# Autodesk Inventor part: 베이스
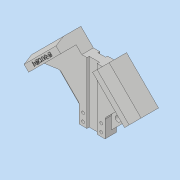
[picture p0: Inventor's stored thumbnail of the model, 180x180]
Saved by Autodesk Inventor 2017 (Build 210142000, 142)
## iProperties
Part Number: 베이스
Material: 일반
Document SubType Name: Modeling
Designer: 222
Density: 1 g/cm^3
Appearance: 기본값
Author: 222
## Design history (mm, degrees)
sketch "스케치1"
  geometry: L1 (-84.853, 0)-(0, 84.853); L2 (0, 84.853)-(84.853, 0); L3 (84.853, 0)-(0, -84.853); L4 (0, -84.853)-(-84.853, 0); 1 further point
  constraints: 8 end point, 2 horizontal alignment, 2 parallel, 2 vertical alignment, 1 perpendicular
  dimensions: "d0" = 120 distance of L1.end L2.end
extrude "돌출1" new body sketch "스케치1" distance "d1" = 42; taper "d2" = 0 deg
sketch "스케치2"
  geometry: L1 (0, 84.853)-(-84.853, 0) reference; L2 (-84.853, 0)-(0, -84.853) reference; L3 (0, -84.853)-(84.853, 0) reference; L4 (84.853, 0)-(0, 84.853) reference; L5 (-74.246, -10.607)-(0, 63.64); L6 (0, 63.64)-(74.246, -10.607); 1 further point
  constraints: 4 end point, 2 point on line, 1 other
  dimensions: "d3" = 15 distance between parallel lines of L1 L5
extrude "돌출2" cut sketch "스케치2" distance "d4" = 24; taper "d5" = 0 deg
sketch "스케치3"
  geometry: L1 (-35.355, 49.497)-(-16.005, 30.147); L2 (-16.005, 30.147)-(16.005, 30.147); L3 (16.005, 30.147)-(35.355, 49.497); L4 (-74.246, -10.607)-(-49.497, -7.071); L5 (0, -84.853)-(-84.853, 0) reference; L6 (-20, -36.569)-(-20, -64.853); L7 (20, -64.853)-(20, -36.569); L8 (20, -36.569)-(49.497, -7.071); L9 (49.497, -7.071)-(74.246, -10.607); L10 (74.246, -10.607)-(0, -84.853) reference; L11 (-74.246, -10.607)-(0, 63.64) reference; L12 (0, 63.64)-(74.246, -10.607) reference; L13 (74.246, -10.607)-(84.853, 0) reference; L14 (84.853, 0)-(0, 84.853) reference; L15 (0, 84.853)-(-84.853, 0) reference; L16 (-84.853, 0)-(-74.246, -10.607) reference; L17 (74.246, -10.607)-(0, -84.853) reference; L18 (0, 63.64)-(74.246, -10.607) reference; L19 (-74.246, -10.607)-(0, 63.64) reference; L20 (0, -84.853)-(-74.246, -10.607) reference; L21 (-49.497, -7.071)-(-20, -36.569); L22 (-20, -64.853)-(20, -64.853); 1 further point
  constraints: 20 end point, 6 point on line, 3 horizontal alignment, 2 horizontal, 2 parallel, 2 perpendicular, 2 vertical
  dimensions: "d6" = 50 distance of L14.end L1.start; "d7" = 50 distance of L3.end L14.end; "d8" = 20 horizontal distance of L6.end L5.start; "d9" = 20 distance from line of L20 L4.end; "d10" = 30 distance from line of L15 L4.end; "d11" = 95 distance between parallel lines of L2 L22
extrude "돌출3" cut sketch "스케치3" stored distance "d14" = 24; taper "d15" = 0 deg
sketch "스케치4"
  geometry: L1 (16.005, 30.147)-(-16.005, 30.147) reference; L2 (-20, -64.853)-(20, -64.853) reference; L3 (-8, 30.147)-(-8, -64.853); L4 (20, -64.853)-(-20, -64.853) reference; L5 (8, -64.853)-(8, 30.147); 1 further point
  constraints: 4 end point, 4 point on line, 1 perpendicular, 1 vertical
  dimensions: "d16" = 16 distance between parallel lines of L5 L3; "d17" = 8 distance from line of L5 point (0, 0)
extrude "돌출4" cut sketch "스케치4" distance "d18" = 3.5; taper "d19" = 0 deg
fillet "모깎기1" dims "d20" = 5
sketch "스케치5"
  geometry: L1 (-8, -64.853)-(-8, 30.147) reference; L2 (-8, 30.147)-(-16.005, 30.147) reference; L3 (-16.005, 30.147)-(-24.749, 38.891) reference; L4 (-74.246, -10.607)-(-24.749, 38.891) reference; L5 (-74.246, -10.607)-(-51.972, -7.425) reference; L6 (-47.73, -8.839)-(-21.464, -35.104) reference; L7 (-20, -38.64)-(-20, -64.853) reference; L8 (-20, -64.853)-(-8, -64.853) reference; L9 (8, 30.147)-(8, -64.853) reference; L10 (8, -64.853)-(20, -64.853) reference; L11 (20, -64.853)-(20, -38.64) reference; L12 (21.464, -35.104)-(47.73, -8.839) reference; L13 (51.972, -7.425)-(74.246, -10.607) reference; L14 (24.749, 38.891)-(74.246, -10.607) reference; L15 (24.749, 38.891)-(16.005, 30.147) reference; L16 (16.005, 30.147)-(8, 30.147) reference; L17 (-68.059, -9.723)-(-20, -57.782); L18 (20, -57.782)-(68.059, -9.723); L19 (-74.246, -10.607)-(-51.972, -7.425) reference; L20 (-20, -38.64)-(-20, -64.853) reference; L21 (20, -64.853)-(20, -38.64) reference; L22 (51.972, -7.425)-(74.246, -10.607) reference; L23 (-47.73, -8.839)-(-21.464, -35.104) reference; L24 (21.464, -35.104)-(47.73, -8.839) reference; L25 (74.246, -10.607)-(84.853, 0) reference; L26 (-84.853, 0)-(-74.246, -10.607) reference; A1 r 5 centre (-51.265, -12.374) between (-47.73, -8.839) and (-51.972, -7.425) reference; A2 r 5 centre (-25, -38.64) between (-20, -38.64) and (-21.464, -35.104) reference; A3 r 5 centre (25, -38.64) between (21.464, -35.104) and (20, -38.64) reference; A4 r 5 centre (51.265, -12.374) between (51.972, -7.425) and (47.73, -8.839) reference; 1 further point
  constraints: 4 end point, 4 point on line, 2 parallel
  dimensions: "d21" = 5 distance between parallel lines of L25 L18; "d22" = 5 distance between parallel lines of L26 L17
extrude "돌출5" join sketch "스케치5" distance "d23" = 8; taper "d24" = 0 deg
sketch "스케치6"
  geometry: L1 (-49.497, -18.385)-(-29.698, -38.184); L2 (-52.326, -21.213)-(-32.527, -41.012); L3 (-26.87, -35.355)-(-46.669, -15.556); L4 (49.497, -18.385)-(29.698, -38.184); L5 (46.669, -15.556)-(26.87, -35.355); L6 (32.527, -41.012)-(52.326, -21.213); L7 (-84.853, 0)-(-74.246, -10.607) reference; L8 (-35.355, 49.497)-(-84.853, 0) reference; L9 (84.853, 0)-(35.355, 49.497) reference; A1 r 4 centre (-49.497, -18.385) between (-46.669, -15.556) and (-52.326, -21.213); A2 r 4 centre (-29.698, -38.184) between (-32.527, -41.012) and (-26.87, -35.355); A3 r 4 centre (49.497, -18.385) between (52.326, -21.213) and (46.669, -15.556); A4 r 4 centre (29.698, -38.184) between (26.87, -35.355) and (32.527, -41.012); 3 further points
  constraints: 16 end point, 8 point on circle, 8 tangent, 4 centre point, 3 horizontal alignment, 2 midpoint, 2 parallel, 1 perpendicular
  dimensions: "d25" = 28 distance of L1.start L1.end; "d26" = 8 diameter of A2; "d27" = 28 distance of L4.start L4.end; "d28" = 8 diameter of A4; "d29" = 12 distance from line of point (-39.598, -28.284) L7; "d30" = 38 distance from line of L1.start L8; "d31" = 38 distance from line of L4.start L9
extrude "돌출6" cut sketch "스케치6" stored distance "d32" = 8; taper "d33" = 0 deg
sketch "스케치7"
  geometry: L1 (-20, -64.853)-(20, -64.853) reference; L2 (16.005, 30.147)-(-16.005, 30.147) reference; L3 (-6, 30.147)-(-6, -64.853); L4 (6, 30.147)-(6, -64.853); 5 further points
  constraints: 4 end point, 4 point on line, 2 horizontal alignment, 2 vertical alignment, 1 vertical
  dimensions: "d34" = 28 distance of point (14, -58.853) point (-14, -58.853); "d35" = 6 distance from line of point (14, -58.853) L1; "d36" = 12 distance of point (14, -46.853) point (14, -58.853); "d37" = 14 horizontal distance of point (0, 0) point (14, -58.853); "d45" = 12 distance between parallel lines of L4 L3; "d46" = 6 distance from line of L4 point (0, 0)
hole "구멍1" sketch "스케치7" diameter "d38" = 4.5; stored, may be unused: countersink angle "d42" = 90 deg, drill point angle "d44" = 118 deg; dims "d39" = 6, "d40" = 8, "d41" = 10, "d43" = 8
extrude "돌출7" cut sketch "스케치7" distance "d47" = 3; taper "d48" = 0 deg
chamfer "모따기1" distance "d49" = 5; stored, may be unused: second distance "d50" = 15, angle "d51" = 45 deg
chamfer "모따기2" distance "d52" = 5; stored, may be unused: second distance "d53" = 15, angle "d54" = 45 deg
sketch "스케치8"
  geometry: L1 (-74.246, -10.607)-(-24.749, 38.891) reference; L2 (-31.82, 45.962)-(-35.355, 49.497) reference; 2 further points
  constraints: 1 other
  dimensions: "d55" = 5 distance from line of L1 point (-53.033, 17.678); "d56" = 35 distance from line of L2 point (-53.033, 17.678)
feature "엠보싱1" sketch "스케치8" dims "d0" = 120, "d57" = 0.5, "d58" = 0
node "솔리드1"
node "투영된 루프1"
node "투영된 루프2"
node "투영된 루프3"
node "투영된 루프4"
node "투영된 루프5"
